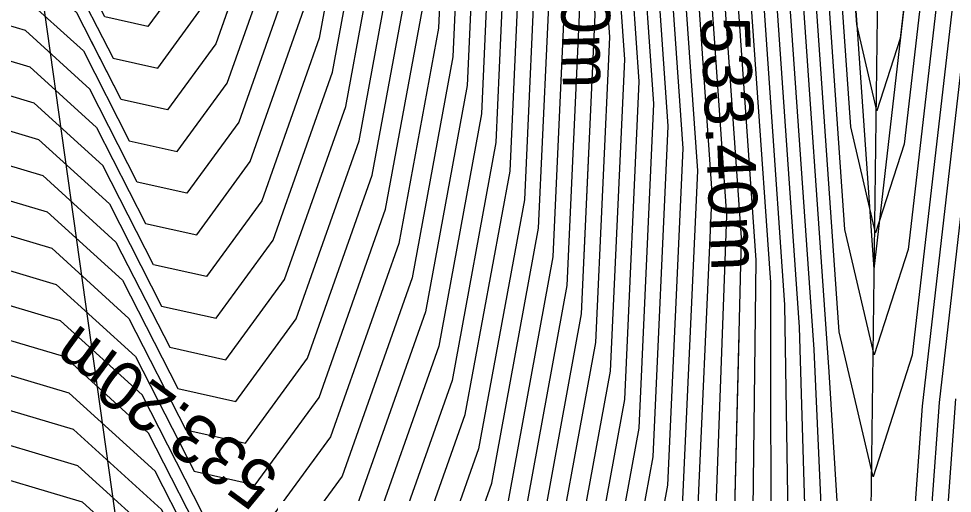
# Model space of a CAD drawing. Extents: x -866683 to -866410, y -1041951 to -1040252.
# Drawn here: x -866454.85 to -866449.11, y -1041932.01 to -1041929.09 of the extents above; entities that cross this region are included whole.
import ezdxf

# ---------------------------------------------------------------- set-up
doc = ezdxf.new("R2010")
doc.units = 0
for name, color, linetype in [('BREAKLINE', 7, 'Continuous'), ('V-VEDL', 7, 'Continuous'), ('V_po_cm', 7, 'Continuous')]:
    doc.layers.add(name, color=color, linetype=linetype)

msp = doc.modelspace()

# ---------------------------------------------------------------- linework, layer by layer
at = {"layer": 'BREAKLINE'}
for points in [[(-866451.679, -1041950.508), (-866455.618, -1041922.473), (-866456.719, -1041912.396), (-866455.207, -1041909.853), (-866453.752, -1041908.342), (-866450, -1041907.538), (-866447.7, -1041908.076), (-866445.165, -1041909.459), (-866437.422, -1041915.176), (-866426.565, -1041925.108), (-866438.22, -1041915.868), (-866445.312, -1041910.554), (-866447.7, -1041908.076)], [(-866430.202, -1041927.282), (-866445.247, -1041913.64), (-866449.543, -1041926.354), (-866449.641, -1041934.033), (-866450.183, -1041936.864), (-866452.267, -1041937.851), (-866451.576, -1041945.087)]]:
    msp.add_lwpolyline(points, dxfattribs=at)
at = {"layer": 'V-VEDL'}
for points in [[(-866449.7169, -1041924.4172), (-866452.0847, -1041924.1217), (-866452.8467, -1041924.414), (-866453.1868, -1041925.1464), (-866453.1051, -1041926.3188), (-866453.1537, -1041927.3927), (-866453.3327, -1041928.3679), (-866453.6421, -1041929.2445), (-866453.9391, -1041929.651), (-866454.2237, -1041929.5876), (-866454.496, -1041929.0541), (-866454.8656, -1041928.7179), (-866455.3324, -1041928.579), (-866456.4607, -1041928.6957)], [(-866449.6778, -1041924.8534), (-866451.5122, -1041924.6245), (-866452.0867, -1041925.0785), (-866452.3185, -1041926.1012), (-866452.2076, -1041927.6924), (-866452.2736, -1041929.1497), (-866452.5165, -1041930.4732), (-866452.9364, -1041931.6628), (-866453.3395, -1041932.2146), (-866453.7258, -1041932.1285), (-866454.0953, -1041931.4045), (-866454.5968, -1041930.9482), (-866455.2304, -1041930.7597), (-866456.7616, -1041930.9181)], [(-866457.0626, -1041933.1405), (-866455.1284, -1041932.9404), (-866454.3281, -1041933.1785), (-866453.6946, -1041933.7549), (-866453.2278, -1041934.6694), (-866452.7398, -1041934.7782), (-866452.2307, -1041934.0812), (-866451.7003, -1041932.5785), (-866451.3935, -1041930.9067), (-866451.3101, -1041929.0659), (-866451.4503, -1041927.056), (-866451.3268, -1041925.7431), (-866450.9398, -1041925.1272), (-866449.6386, -1041925.2896)], [(-866449.5994, -1041925.7259), (-866450.3673, -1041925.63), (-866450.5669, -1041926.4076), (-866450.582, -1041928.0107), (-866450.4127, -1041930.4394), (-866450.4641, -1041932.5242), (-866450.7364, -1041934.2652), (-866451.2295, -1041935.6623), (-866451.5972, -1041936.6715), (-866451.8395, -1041937.2927), (-866451.9565, -1041937.526), (-866451.8502, -1041937.6044), (-866451.5207, -1041937.5279), (-866450.9679, -1041937.2965), (-866450.586, -1041937.3604), (-866450.3749, -1041937.7197), (-866450.2943, -1041939.0287)], [(-866449.5602, -1041926.1621), (-866449.7949, -1041926.1328), (-866449.8381, -1041926.6244), (-866449.8073, -1041927.6224), (-866449.5976, -1041930.6309)], [(-866449.5602, -1041926.1621), (-866449.5002, -1041926.1463), (-866449.4401, -1041926.1673), (-866449.3499, -1041926.2172), (-866449.2297, -1041926.296), (-866449.2038, -1041926.8214), (-866449.2722, -1041927.7935), (-866449.5976, -1041930.6309)]]:
    msp.add_lwpolyline(points, dxfattribs=at)
at = {"layer": 'V_po_cm'}
for points in [[(-866449.0913, -1041924.1632), (-866449.408, -1041924.2466), (-866450.0316, -1041924.2507), (-866450.962, -1041924.1756), (-866452.1992, -1041924.0211), (-866452.9987, -1041924.2811), (-866453.3605, -1041924.9554), (-866453.2846, -1041926.0441), (-866453.3297, -1041927.0413), (-866453.4959, -1041927.9468), (-866453.7832, -1041928.7608), (-866454.059, -1041929.1383), (-866454.3233, -1041929.0794), (-866454.5761, -1041928.584), (-866454.9193, -1041928.2718)], [(-866454.8924, -1041928.4949), (-866454.5361, -1041928.819), (-866454.2735, -1041929.3335), (-866453.999, -1041929.3947), (-866453.7126, -1041929.0026), (-866453.4143, -1041928.1573), (-866453.2417, -1041927.217), (-866453.1948, -1041926.1815), (-866453.2736, -1041925.0509), (-866452.9227, -1041924.3476), (-866452.1419, -1041924.0714), (-866450.9314, -1041924.2225), (-866450.0211, -1041924.296), (-866449.4109, -1041924.292), (-866449.101, -1041924.2104)], [(-866455.3222, -1041928.797), (-866454.8387, -1041928.9409), (-866454.4559, -1041929.2891), (-866454.1739, -1041929.8416), (-866453.8791, -1041929.9074), (-866453.5715, -1041929.4863), (-866453.2511, -1041928.5784), (-866453.0657, -1041927.5684), (-866453.0153, -1041926.4562), (-866453.1, -1041925.2419), (-866452.7707, -1041924.4805), (-866452.0274, -1041924.172), (-866450.8702, -1041924.3164), (-866450, -1041924.3867), (-866449.4168, -1041924.3828), (-866449.1205, -1041924.3048), (-866448.5277, -1041924.512)], [(-866448.5511, -1041924.5544), (-866449.1302, -1041924.352), (-866449.4197, -1041924.4282), (-866449.9895, -1041924.432), (-866450.8397, -1041924.3634), (-866451.9702, -1041924.2223), (-866452.6947, -1041924.5469), (-866453.0132, -1041925.3373), (-866452.9256, -1041926.5935), (-866452.9777, -1041927.7441), (-866453.1695, -1041928.7889), (-866453.5009, -1041929.7281), (-866453.8191, -1041930.1637), (-866454.1241, -1041930.0957), (-866454.4159, -1041929.5242), (-866454.8118, -1041929.164), (-866455.312, -1041929.0151)], [(-866455.3018, -1041929.2332), (-866454.785, -1041929.387), (-866454.3758, -1041929.7592), (-866454.0743, -1041930.3498), (-866453.7592, -1041930.4201), (-866453.4304, -1041929.97), (-866453.0878, -1041928.9995), (-866452.8897, -1041927.9198), (-866452.8358, -1041926.7309), (-866452.9263, -1041925.4328), (-866452.6187, -1041924.6134), (-866451.9129, -1041924.2725), (-866450.8091, -1041924.4103), (-866449.9789, -1041924.4773), (-866449.4226, -1041924.4737), (-866449.14, -1041924.3993), (-866448.5745, -1041924.5969)], [(-866448.5979, -1041924.6393), (-866449.1497, -1041924.4465), (-866449.4255, -1041924.5191), (-866449.9684, -1041924.5227), (-866450.7785, -1041924.4573), (-866451.8557, -1041924.3228), (-866452.5427, -1041924.6798), (-866452.8395, -1041925.5283), (-866452.7461, -1041926.8682), (-866452.8017, -1041928.0955), (-866453.0062, -1041929.21), (-866453.3598, -1041930.2118), (-866453.6992, -1041930.6764), (-866454.0245, -1041930.6039), (-866454.3357, -1041929.9942), (-866454.7581, -1041929.61), (-866455.2916, -1041929.4513)], [(-866455.2814, -1041929.6693), (-866454.7312, -1041929.833), (-866454.2956, -1041930.2293), (-866453.9747, -1041930.858), (-866453.6393, -1041930.9328), (-866453.2892, -1041930.4536), (-866452.9246, -1041929.4205), (-866452.7136, -1041928.2712), (-866452.6563, -1041927.0056), (-866452.7527, -1041925.6238), (-866452.4667, -1041924.7463), (-866451.7985, -1041924.3731), (-866450.7479, -1041924.5042), (-866449.9579, -1041924.568), (-866449.4284, -1041924.5645), (-866449.1594, -1041924.4937), (-866448.6213, -1041924.6818)], [(-866455.2712, -1041929.8874), (-866454.7043, -1041930.0561), (-866454.2556, -1041930.4643), (-866453.9249, -1041931.1121), (-866453.5793, -1041931.1892), (-866453.2186, -1041930.6955), (-866452.843, -1041929.6311), (-866452.6256, -1041928.4469), (-866452.5666, -1041927.143), (-866452.6658, -1041925.7193), (-866452.3907, -1041924.8127), (-866451.7412, -1041924.4234), (-866450.7173, -1041924.5511), (-866449.9474, -1041924.6133), (-866449.4313, -1041924.6099), (-866449.1692, -1041924.5409), (-866448.6447, -1041924.7242)], [(-866455.261, -1041930.1055), (-866454.6775, -1041930.2791), (-866454.2155, -1041930.6994), (-866453.8751, -1041931.3662), (-866453.5193, -1041931.4455), (-866453.1481, -1041930.9373), (-866452.7614, -1041929.8416), (-866452.5376, -1041928.6226), (-866452.4768, -1041927.2803), (-866452.579, -1041925.8147), (-866452.3147, -1041924.8792), (-866451.684, -1041924.4736), (-866450.6867, -1041924.5981), (-866449.9368, -1041924.6587), (-866449.4342, -1041924.6553), (-866449.1789, -1041924.5881), (-866448.6681, -1041924.7666)], [(-866455.2508, -1041930.3235), (-866454.6506, -1041930.5021), (-866454.1754, -1041930.9344), (-866453.8253, -1041931.6203), (-866453.4594, -1041931.7019), (-866453.0775, -1041931.1792), (-866452.6798, -1041930.0521), (-866452.4496, -1041928.7983), (-866452.3871, -1041927.4177), (-866452.4922, -1041925.9102), (-866452.2387, -1041924.9456), (-866451.6267, -1041924.5239), (-866450.6562, -1041924.645), (-866449.9263, -1041924.704), (-866449.4371, -1041924.7008), (-866449.1886, -1041924.6353), (-866448.6915, -1041924.8091)], [(-866455.2406, -1041930.5416), (-866454.6237, -1041930.7252), (-866454.1354, -1041931.1694), (-866453.7756, -1041931.8744), (-866453.3994, -1041931.9582), (-866453.0069, -1041931.421), (-866452.5981, -1041930.2627), (-866452.3616, -1041928.974), (-866452.2973, -1041927.555), (-866452.4054, -1041926.0057), (-866452.1627, -1041925.0121), (-866451.5695, -1041924.5742), (-866450.6256, -1041924.692), (-866449.9158, -1041924.7493), (-866449.44, -1041924.7462), (-866449.1984, -1041924.6826), (-866448.7149, -1041924.8515)], [(-866448.7617, -1041924.9364), (-866449.2179, -1041924.777), (-866449.4459, -1041924.837), (-866449.8947, -1041924.84), (-866450.5644, -1041924.7859), (-866451.455, -1041924.6747), (-866452.0107, -1041925.145), (-866452.2317, -1041926.1967), (-866452.1179, -1041927.8297), (-866452.1856, -1041929.3254), (-866452.4349, -1041930.6837), (-866452.8658, -1041931.9047), (-866453.2795, -1041932.4709), (-866453.676, -1041932.3826), (-866454.0552, -1041931.6395), (-866454.57, -1041931.1712), (-866455.2202, -1041930.9777)], [(-866448.7851, -1041924.9789), (-866449.2276, -1041924.8242), (-866449.4488, -1041924.8824), (-866449.8842, -1041924.8853), (-866450.5338, -1041924.8328), (-866451.3977, -1041924.725), (-866451.9348, -1041925.2115), (-866452.1449, -1041926.2921), (-866452.0281, -1041927.9671), (-866452.0976, -1041929.5011), (-866452.3533, -1041930.8942), (-866452.7952, -1041932.1465), (-866453.2195, -1041932.7273), (-866453.6262, -1041932.6367), (-866454.0151, -1041931.8745), (-866454.5431, -1041931.3943), (-866455.21, -1041931.1958)], [(-866448.8085, -1041925.0213), (-866449.2373, -1041924.8714), (-866449.4517, -1041924.9279), (-866449.8736, -1041924.9306), (-866450.5033, -1041924.8798), (-866451.3405, -1041924.7753), (-866451.8588, -1041925.2779), (-866452.058, -1041926.3876), (-866451.9384, -1041928.1044), (-866452.0096, -1041929.6768), (-866452.2717, -1041931.1048), (-866452.7247, -1041932.3883), (-866453.1596, -1041932.9837), (-866453.5764, -1041932.8907), (-866453.9751, -1041932.1096), (-866454.5162, -1041931.6173), (-866455.1998, -1041931.4139)], [(-866448.8318, -1041925.0637), (-866449.2471, -1041924.9186), (-866449.4546, -1041924.9733), (-866449.8631, -1041924.976), (-866450.4727, -1041924.9267), (-866451.2833, -1041924.8256), (-866451.7828, -1041925.3444), (-866451.9712, -1041926.4831), (-866451.8486, -1041928.2418), (-866451.9216, -1041929.8525), (-866452.19, -1041931.3153), (-866452.6541, -1041932.6302), (-866453.0996, -1041933.24), (-866453.5266, -1041933.1448), (-866453.935, -1041932.3446), (-866454.4894, -1041931.8403), (-866455.1896, -1041931.632)], [(-866455.1794, -1041931.85), (-866454.4625, -1041932.0634), (-866453.8949, -1041932.5797), (-866453.4768, -1041933.3989), (-866453.0396, -1041933.4964), (-866452.5835, -1041932.872), (-866452.1084, -1041931.5258), (-866451.8335, -1041930.0282), (-866451.7589, -1041928.3791), (-866451.8844, -1041926.5786), (-866451.7068, -1041925.4108), (-866451.226, -1041924.8759), (-866450.4421, -1041924.9737), (-866449.8526, -1041925.0213), (-866449.4575, -1041925.0187), (-866449.2568, -1041924.9659), (-866448.8552, -1041925.1062)], [(-866448.8786, -1041925.1486), (-866449.2665, -1041925.0131), (-866449.4604, -1041925.0641), (-866449.8421, -1041925.0666), (-866450.4115, -1041925.0206), (-866451.1688, -1041924.9261), (-866451.6308, -1041925.4773), (-866451.7976, -1041926.674), (-866451.6691, -1041928.5165), (-866451.7455, -1041930.2039), (-866452.0268, -1041931.7364), (-866452.513, -1041933.1139), (-866452.9797, -1041933.7527), (-866453.427, -1041933.653), (-866453.8549, -1041932.8147), (-866454.4356, -1041932.2864), (-866455.1692, -1041932.0681)], [(-866455.159, -1041932.2862), (-866454.4087, -1041932.5094), (-866453.8148, -1041933.0497), (-866453.3772, -1041933.9071), (-866452.9197, -1041934.0091), (-866452.4424, -1041933.3557), (-866451.9452, -1041931.9469), (-866451.6575, -1041930.3796), (-866451.5794, -1041928.6538), (-866451.7107, -1041926.7695), (-866451.5548, -1041925.5437), (-866451.1115, -1041924.9764), (-866450.3809, -1041925.0676), (-866449.8315, -1041925.112), (-866449.4633, -1041925.1095), (-866449.2763, -1041925.0603), (-866448.902, -1041925.1911)], [(-866448.9254, -1041925.2335), (-866449.286, -1041925.1075), (-866449.4662, -1041925.1549), (-866449.821, -1041925.1573), (-866450.3503, -1041925.1145), (-866451.0543, -1041925.0267), (-866451.4788, -1041925.6102), (-866451.6239, -1041926.865), (-866451.4896, -1041928.7912), (-866451.5695, -1041930.5553), (-866451.8636, -1041932.1574), (-866452.3718, -1041933.5975), (-866452.8598, -1041934.2654), (-866453.3274, -1041934.1612), (-866453.7747, -1041933.2848), (-866454.3819, -1041932.7325), (-866455.1488, -1041932.5042)], [(-866455.1386, -1041932.7223), (-866454.355, -1041932.9555), (-866453.7347, -1041933.5198), (-866453.2776, -1041934.4153), (-866452.7998, -1041934.5218), (-866452.3012, -1041933.8394), (-866451.782, -1041932.368), (-866451.4815, -1041930.731), (-866451.3999, -1041928.9285), (-866451.5371, -1041926.9605), (-866451.4028, -1041925.6766), (-866450.997, -1041925.077), (-866450.3198, -1041925.1615), (-866449.8105, -1041925.2026), (-866449.4691, -1041925.2004), (-866449.2957, -1041925.1547), (-866448.9488, -1041925.276)], [(-866455.1182, -1041933.1585), (-866454.3013, -1041933.4016), (-866453.6545, -1041933.9899), (-866453.178, -1041934.9235), (-866452.6799, -1041935.0345), (-866452.1601, -1041934.323), (-866451.6187, -1041932.789), (-866451.3055, -1041931.0824), (-866451.2204, -1041929.2032), (-866451.3634, -1041927.1514), (-866451.2508, -1041925.8095), (-866450.8825, -1041925.1775), (-866450.2586, -1041925.2554), (-866449.7894, -1041925.2933), (-866449.4749, -1041925.2912), (-866449.3152, -1041925.2491), (-866448.9956, -1041925.3608)], [(-866449.019, -1041925.4033), (-866449.3249, -1041925.2964), (-866449.4778, -1041925.3366), (-866449.7789, -1041925.3386), (-866450.228, -1041925.3023), (-866450.8253, -1041925.2278), (-866451.1748, -1041925.876), (-866451.2766, -1041927.2469), (-866451.1306, -1041929.3406), (-866451.2175, -1041931.2581), (-866451.5371, -1041932.9996), (-866452.0895, -1041934.5649), (-866452.6199, -1041935.2909), (-866453.1282, -1041935.1776), (-866453.6144, -1041934.2249), (-866454.2744, -1041933.6246), (-866455.108, -1041933.3765)], [(-866449.0424, -1041925.4457), (-866449.3347, -1041925.3436), (-866449.4808, -1041925.382), (-866449.7683, -1041925.3839), (-866450.1974, -1041925.3493), (-866450.768, -1041925.2781), (-866451.0988, -1041925.9424), (-866451.1898, -1041927.3424), (-866451.0409, -1041929.4779), (-866451.1295, -1041931.4338), (-866451.4555, -1041933.2101), (-866452.019, -1041934.8067), (-866452.5599, -1041935.5472), (-866453.0784, -1041935.4317), (-866453.5744, -1041934.46), (-866454.2475, -1041933.8476), (-866455.0978, -1041933.5946)], [(-866449.0658, -1041925.4882), (-866449.3444, -1041925.3908), (-866449.4837, -1041925.4275), (-866449.7578, -1041925.4293), (-866450.1669, -1041925.3962), (-866450.7108, -1041925.3283), (-866451.0228, -1041926.0089), (-866451.1029, -1041927.4379), (-866450.9511, -1041929.6153), (-866451.0414, -1041931.6095), (-866451.3739, -1041933.4206), (-866451.9484, -1041935.0486), (-866452.5, -1041935.8036), (-866453.0286, -1041935.6857), (-866453.5343, -1041934.695), (-866454.2206, -1041934.0707), (-866455.0876, -1041933.8127)], [(-866455.0774, -1041934.0307), (-866454.1938, -1041934.2937), (-866453.4942, -1041934.9301), (-866452.9788, -1041935.9398), (-866452.44, -1041936.06), (-866451.8778, -1041935.2904), (-866451.2923, -1041933.6312), (-866450.9534, -1041931.7852), (-866450.8614, -1041929.7526), (-866451.0161, -1041927.5333), (-866450.9468, -1041926.0753), (-866450.6536, -1041925.3786), (-866450.1363, -1041925.4432), (-866449.7473, -1041925.4746), (-866449.4866, -1041925.4729), (-866449.3541, -1041925.438), (-866449.0892, -1041925.5306)], [(-866449.1126, -1041925.5731), (-866449.3639, -1041925.4852), (-866449.4895, -1041925.5183), (-866449.7368, -1041925.5199), (-866450.1057, -1041925.4901), (-866450.5963, -1041925.4289), (-866450.8708, -1041926.1418), (-866450.9293, -1041927.6288), (-866450.7716, -1041929.89), (-866450.8654, -1041931.9609), (-866451.2106, -1041933.8417), (-866451.8073, -1041935.5322), (-866452.3801, -1041936.3163)], [(-866448.7794, -1041925.8129), (-866449.136, -1041925.6155), (-866449.3736, -1041925.5324), (-866449.4924, -1041925.5637), (-866449.7262, -1041925.5653), (-866450.0751, -1041925.5371), (-866450.5391, -1041925.4792), (-866450.7948, -1041926.2083), (-866450.8425, -1041927.7243), (-866450.6819, -1041930.0273), (-866450.7774, -1041932.1366), (-866451.129, -1041934.0522), (-866451.7367, -1041935.7741), (-866452.3201, -1041936.5727)], [(-866448.8233, -1041925.844), (-866449.1594, -1041925.6579), (-866449.3833, -1041925.5797), (-866449.4953, -1041925.6091), (-866449.7157, -1041925.6106), (-866450.0445, -1041925.584), (-866450.4818, -1041925.5295), (-866450.7189, -1041926.2747), (-866450.7556, -1041927.8198), (-866450.5921, -1041930.1647), (-866450.6894, -1041932.3123), (-866451.0474, -1041934.2627), (-866451.6661, -1041936.0159), (-866452.2601, -1041936.829)], [(-866448.8672, -1041925.8751), (-866449.1827, -1041925.7004), (-866449.3931, -1041925.6269), (-866449.4982, -1041925.6546), (-866449.7052, -1041925.6559), (-866450.014, -1041925.631), (-866450.4246, -1041925.5797), (-866450.6429, -1041926.3412), (-866450.6688, -1041927.9153), (-866450.5024, -1041930.302), (-866450.5811, -1041932.4306), (-866450.9049, -1041934.3009), (-866452.0428, -1041937.5251)], [(-866448.955, -1041925.9373), (-866449.2295, -1041925.7853), (-866449.4126, -1041925.7213), (-866449.504, -1041925.7454), (-866449.6841, -1041925.7466), (-866449.9528, -1041925.7249), (-866450.3101, -1041925.6803), (-866450.4909, -1041926.4741), (-866450.4951, -1041928.1062), (-866450.3229, -1041930.5767), (-866450.3472, -1041932.6178), (-866450.5679, -1041934.2295), (-866451.4023, -1041936.5939)], [(-866448.9988, -1041925.9684), (-866449.2529, -1041925.8277), (-866449.4223, -1041925.7685), (-866449.5069, -1041925.7908), (-866449.6736, -1041925.7919), (-866449.9222, -1041925.7718), (-866450.2528, -1041925.7306), (-866450.4149, -1041926.5405), (-866450.4083, -1041928.2017), (-866450.2332, -1041930.7141), (-866450.2302, -1041932.7114), (-866450.3994, -1041934.1937), (-866451.0821, -1041936.1282)], [(-866450.7619, -1041935.6626), (-866450.2308, -1041934.158), (-866450.1132, -1041932.8051), (-866450.1434, -1041930.8514), (-866450.3215, -1041928.2972), (-866450.3389, -1041926.607), (-866450.1956, -1041925.7808), (-866449.8916, -1041925.8188), (-866449.663, -1041925.8372), (-866449.5098, -1041925.8362), (-866449.432, -1041925.8157), (-866449.2763, -1041925.8702), (-866449.0427, -1041925.9995)], [(-866450.4416, -1041935.197), (-866450.0623, -1041934.1223), (-866449.9962, -1041932.8987), (-866450.0537, -1041930.9888), (-866450.2347, -1041928.3927), (-866450.2629, -1041926.6734), (-866450.1383, -1041925.8311), (-866449.861, -1041925.8657), (-866449.6525, -1041925.8826), (-866449.5128, -1041925.8816), (-866449.4418, -1041925.863), (-866449.2997, -1041925.9126), (-866449.0866, -1041926.0306)], [(-866450.1214, -1041934.7314), (-866449.8938, -1041934.0866), (-866449.8792, -1041932.9923), (-866449.9639, -1041931.1261), (-866450.1478, -1041928.4881), (-866450.1869, -1041926.7399), (-866450.0811, -1041925.8814), (-866449.8305, -1041925.9127), (-866449.642, -1041925.9279), (-866449.5157, -1041925.9271), (-866449.4515, -1041925.9102), (-866449.3231, -1041925.955), (-866449.1305, -1041926.0617), (-866448.8737, -1041926.2301)], [(-866448.9449, -1041926.2432), (-866449.1744, -1041926.0928), (-866449.3465, -1041925.9975), (-866449.4612, -1041925.9574), (-866449.5186, -1041925.9725), (-866449.6315, -1041925.9732), (-866449.7999, -1041925.9596), (-866450.0239, -1041925.9317), (-866450.1109, -1041926.8063), (-866450.061, -1041928.5836), (-866449.8742, -1041931.2635), (-866449.7623, -1041933.0859), (-866449.7253, -1041934.0509), (-866449.8011, -1041934.2658)], [(-866452.2356, -1041928.3117), (-866452.2736, -1041929.1497), (-866452.5165, -1041930.4732), (-866452.9364, -1041931.6628), (-866453.0597, -1041931.8316)], [(-866449.3445, -1041928.4242), (-866449.4349, -1041929.2122), (-866449.5783, -1041929.6566), (-866449.7025, -1041929.1267), (-866449.7439, -1041928.5324)], [(-866453.3954, -1041928.5454), (-866453.6421, -1041929.2445), (-866453.9391, -1041929.651), (-866454.2237, -1041929.5876), (-866454.4365, -1041929.1706)], [(-866448.9066, -1041928.9254), (-866449.1964, -1041931.4523), (-866449.3373, -1041933.3952), (-866449.3293, -1041934.7542), (-866449.1723, -1041935.5291), (-866449.206, -1041936.276), (-866449.4305, -1041936.9949), (-866449.8456, -1041937.6858), (-866450.1318, -1041937.9939), (-866450.2889, -1041937.9193), (-866450.3171, -1041937.4619), (-866450.4646, -1041937.2109), (-866450.7315, -1041937.1663), (-866451.504, -1041937.4896)], [(-866451.3901, -1041937.4357), (-866450.6842, -1041937.1402), (-866450.4403, -1041937.181), (-866450.3055, -1041937.4104), (-866450.2798, -1041937.8283), (-866450.1362, -1041937.8965), (-866449.8747, -1041937.615), (-866449.4954, -1041936.9836), (-866449.2951, -1041936.3031), (-866449.2738, -1041935.5732), (-866449.4316, -1041934.7942), (-866449.4397, -1041933.428), (-866449.2981, -1041931.4746), (-866449.0067, -1041928.9342)], [(-866452.0741, -1041933.6376), (-866451.7003, -1041932.5785), (-866451.3935, -1041930.9067), (-866451.3487, -1041929.9179)], [(-866450.4275, -1041931.0422), (-866450.4641, -1041932.5242), (-866450.7364, -1041934.2652), (-866451.0388, -1041935.1221)], [(-866449.0948, -1041931.43), (-866449.2349, -1041933.3625), (-866449.2269, -1041934.7142), (-866449.0708, -1041935.485), (-866449.117, -1041936.249), (-866449.3656, -1041937.0062), (-866449.8165, -1041937.7566), (-866450.1274, -1041938.0913), (-866450.2981, -1041938.0103), (-866450.3286, -1041937.5135), (-866450.4889, -1041937.2408), (-866450.7788, -1041937.1923), (-866451.6179, -1041937.5436)]]:
    msp.add_lwpolyline(points, dxfattribs=at)
for points in [[(-866449.4204, -1041925.9913), (-866449.0161, -1041926.2564), (-866448.9725, -1041927.1401), (-866449.0875, -1041928.775), (-866449.3612, -1041931.161), (-866449.6024, -1041931.9084), (-866449.8112, -1041931.0171), (-866449.9875, -1041928.4872), (-866450.0394, -1041926.8088), (-866449.9666, -1041925.9819), (-866449.7693, -1041926.0066), (-866449.6209, -1041926.0186), (-866449.5215, -1041926.0179)], [(-866449.437, -1041926.0403), (-866449.0873, -1041926.2696), (-866449.0496, -1041927.0339), (-866449.1491, -1041928.4478), (-866449.3857, -1041930.5114), (-866449.5944, -1041931.1578), (-866449.7749, -1041930.387), (-866449.9275, -1041928.1989), (-866449.9723, -1041926.7474), (-866449.9094, -1041926.0322), (-866449.7387, -1041926.0535), (-866449.6104, -1041926.0639), (-866449.5244, -1041926.0633)], [(-866449.4536, -1041926.0893), (-866449.1585, -1041926.2828), (-866449.1267, -1041926.9277), (-866449.2106, -1041928.1207), (-866449.4103, -1041929.8618), (-866449.5863, -1041930.4072), (-866449.7387, -1041929.7568), (-866449.8674, -1041927.9107), (-866449.9052, -1041926.6859), (-866449.8521, -1041926.0825), (-866449.7081, -1041926.1005), (-866449.5999, -1041926.1092), (-866449.5273, -1041926.1087)]]:
    msp.add_lwpolyline(points, close=True, dxfattribs=at)

# ---------------------------------------------------------------- texts
for s, rotation, p in [('533.30m', 271.32104, (-866451.5438, -1041927.9609)), ('533.40m', 272.43951, (-866450.661, -1041929.0854)), ('533.20m', 143.74614, (-866453.2373, -1041931.8874))]:
    msp.add_text(s, height=0.3, rotation=rotation, dxfattribs=at).set_placement(p)

doc.saveas('drawing.dxf')
